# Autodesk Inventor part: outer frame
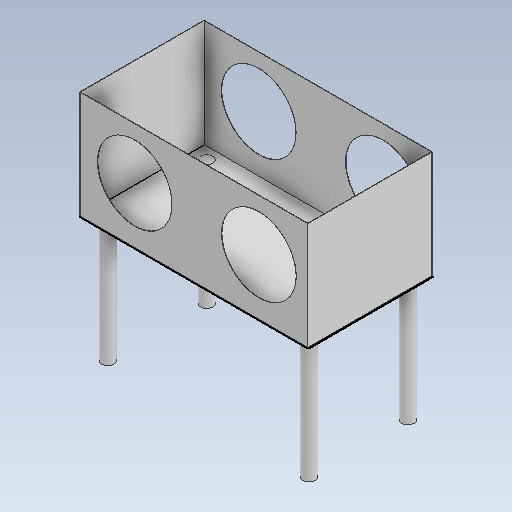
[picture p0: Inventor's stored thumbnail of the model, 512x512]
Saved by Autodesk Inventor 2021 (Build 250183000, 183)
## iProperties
Created: 2021-07
Part Number: outer frame
Material: Generic
Document SubType Name: Modeling
Designer: CHIRAG
Density: 1 g/cm^3
Appearance: Default
Author: CHIRAG
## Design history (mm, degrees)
sketch "Sketch1"
  geometry: L1 (0, 0)-(550, 0); L2 (550, 0)-(550, 260); L3 (550, 260)-(0, 260); L4 (0, 260)-(0, 0)
  constraints: 8 end point, 2 parallel, 1 horizontal, 1 perpendicular
  dimensions: "d0" = 550 distance of L3.end L2.end; "d1" = 260 distance of L2.end L1.end
extrude "Extrusion1" new body sketch "Sketch1" distance "d2" = 300; taper "d3" = 0 deg
shell "Shell1" dims "d4" = 1
sketch "Sketch2"
  geometry: C1 r 90 at (132.488, 135.919); C2 r 90 at (431.767, 135.919); 1 further point
  constraints: 2 centre point
  dimensions: "d5" = 180 diameter of C1; "d6" = 180 diameter of C2
extrude "Extrusion2" cut sketch "Sketch2" distance "d7" = 300; taper "d8" = 0 deg
sketch "Sketch3"
  geometry: C1 r 15 at (34.73, 28.727); C2 r 15 at (34.73, 267.121); C3 r 15 at (520.092, 267.121); C4 r 15 at (520.092, 28.727); 1 further point
  constraints: 4 centre point
  dimensions: "d9" = 30 diameter of C1; "d10" = 30 diameter of C2; "d11" = 30 diameter of C3; "d12" = 30 diameter of C4
extrude "Extrusion3" join sketch "Sketch3" distance "d13" = 300; taper "d14" = 0 deg
sketch "Sketch4"
  geometry: L1 (550, 0)-(550, 300) reference; L2 (0, 0)-(0, 300) reference; L3 (550, 0)-(0, 0); L4 (0, 0)-(0, 300); L5 (0, 300)-(550, 300); L6 (550, 300)-(550, 0)
  constraints: 8 end point, 2 parallel, 1 horizontal, 1 perpendicular
body "Solid1"
